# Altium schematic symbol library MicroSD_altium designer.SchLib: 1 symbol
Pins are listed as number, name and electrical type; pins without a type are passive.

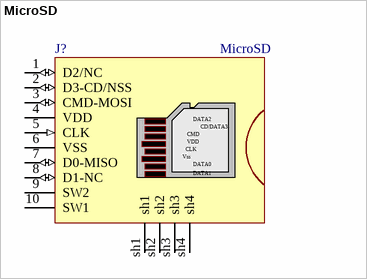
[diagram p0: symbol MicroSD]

## MicroSD
designator J?
MicroSD_altium designer (M.Hariri)
footprint MicroSD_1
pins: 1 D2/NC (io) "Data Bit 2", 2 D3-CD/NSS (io) "Card Detect/Data Bit 3", 3 CMD-MOSI (io) "Command Line", 4 VDD (power) "Supply Voltage 2.7V/3.3V", 5 CLK (in) "Clock", 6 VSS (power) "Ground", 7 D0-MISO (io) "Data Bit 0", 8 D1-NC (io) "Data Bit 1", 9 SW2 "Data Bit 1", 10 SW1 hidden "Data Bit 1", sh1 "Data Bit 1", sh2, sh3, sh4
